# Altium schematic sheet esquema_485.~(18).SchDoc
size A4
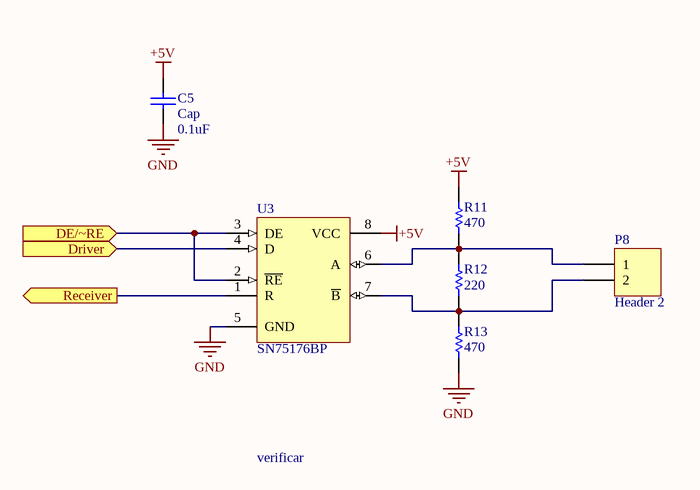
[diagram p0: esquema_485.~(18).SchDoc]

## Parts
C5  Cap  value 0.1uF  [CAPPR2.5-6.3X5]
P8  Header 2  [HDR1X2]
R11  value 470  [AXIAL-0.3]  (hidden comment: Carbon 1/8w 5%)
R12  value 220  [AXIAL-0.3]  (hidden comment: Carbon 1/8w 5%)
R13  value 470  [AXIAL-0.3]  (hidden comment: Carbon 1/8w 5%)
U3  SN75176BP  [626-05]

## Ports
DE/~RE (in), Driver (in), Receiver (out)

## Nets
+5V: C5.2 R11.2 U3.8(VCC)
GND: C5.1 R13.1 U3.5(GND)
DE/~RE: U3.2(~{RE}) U3.3(DE) ; port DE/~RE
Driver: U3.4(D) ; port Driver
Receiver: U3.1(R) ; port Receiver
NetP8_1: P8.1 R11.1 R12.2 U3.6(A)
NetP8_2: P8.2 R12.1 R13.2 U3.7(~{B})

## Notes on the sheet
- verificar

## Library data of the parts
C5 = Cap: Capacitor
P8 = Header 2: Header, 2-Pin
R11-R13 = Res Semi: Semiconductor Resistor
U3 = SN75176BP: Differential Bus Transceiver; Note: Receiver Hysteresis of 50mV Typical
